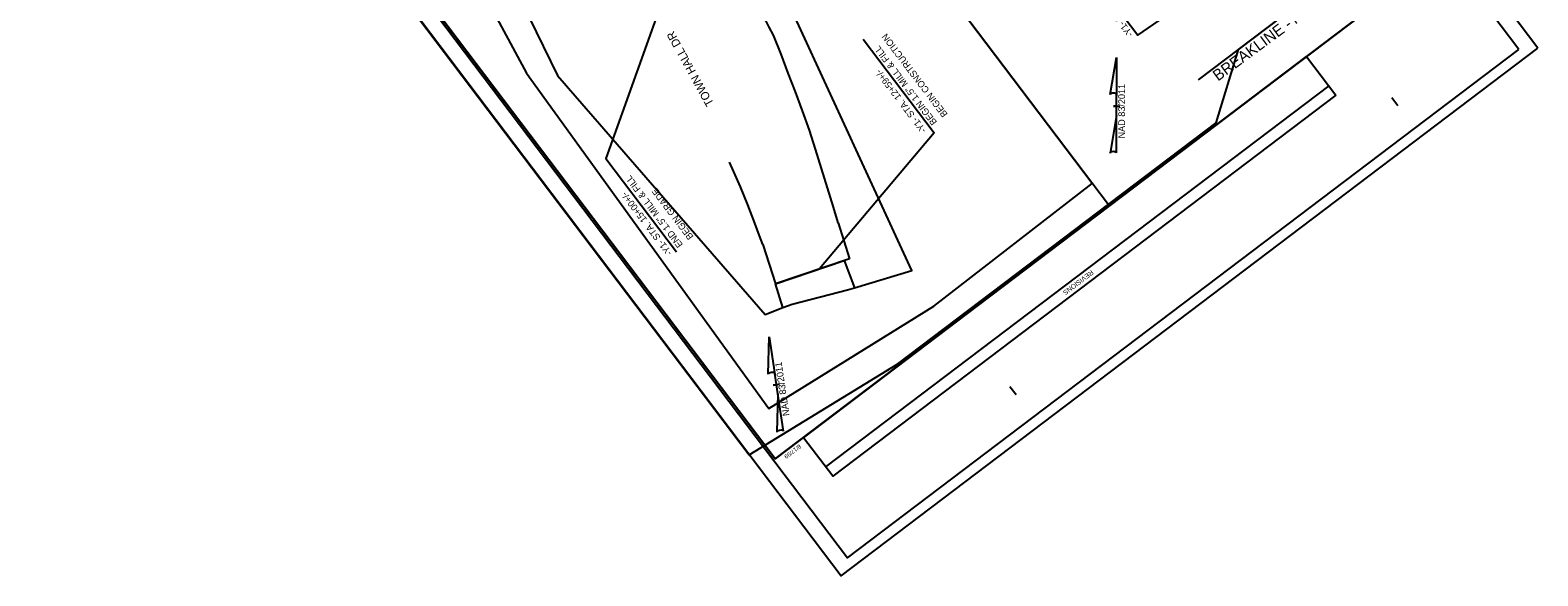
# Model space of a CAD drawing. Extents: x 2046295 to 2051060, y 758814 to 763808.
# Drawn here: x 2046295 to 2047429, y 758814 to 759224 of the extents above; entities that cross this region are included whole.
import ezdxf

# ---------------------------------------------------------------- set-up
doc = ezdxf.new("R2010")
doc.units = 0
for name, color, linetype in [('Matchline', 7, 'Continuous'), ('Matchline Text', 7, 'Continuous'), ('Prop Dimension', 7, 'Continuous'), ('Prop DSN Text', 7, 'Continuous'), ('Prop EOT', 7, 'Continuous'), ('Prop North Arrow NAD83 for Plan Sheets CELL', 7, 'Continuous'), ('Scratch_Level_0', 7, 'Continuous'), ('Scratch_Level_3', 7, 'Continuous'), ('Sheet Block Revision CELL', 7, 'Continuous'), ('Sheet Clip Boundary CELL', 7, 'Continuous'), ('Sheet Cutting Line CELL', 7, 'Continuous'), ('Sheet Plan CELL', 7, 'Continuous'), ('Sheet Plot Border Inside CELL', 7, 'Continuous'), ('Sheet Plot Border Outside CELL', 7, 'Continuous')]:
    doc.layers.add(name, color=color, linetype=linetype)

msp = doc.modelspace()

# ---------------------------------------------------------------- linework, layer by layer
at = {"layer": 'Matchline'}
msp.add_line((2047173.6, 759186.3), (2047315.8, 759294), dxfattribs=at)
at = {"layer": 'Prop DSN Text'}
for points in [[(2047066.4, 759301.2), (2047128, 759219.8), (2047216.9, 759281.2)], [(2046774.7, 759257.7), (2046728, 759127.3), (2046781.2, 759057.1)], [(2046921.6, 759216.8), (2046974.8, 759146.6), (2046888.8, 759044.2)]]:
    msp.add_lwpolyline(points, dxfattribs=at)
at = {"layer": 'Prop EOT'}
for p, q in [((2046902.8, 759078.9), (2046911.2, 759051.8)), ((2046846.1, 759062.5), (2046855.7, 759033.1)), ((2046911.2, 759051.8), (2046855.7, 759033.1))]:
    msp.add_line(p, q, dxfattribs=at)
for points in [[(2046902.8, 759078.9), (2046899.1, 759090.7), (2046894.6, 759105.1), (2046890.2, 759119.6), (2046885.7, 759134.2), (2046881.1, 759148.6), (2046876, 759162.9), (2046870.6, 759177.2), (2046865.2, 759191.4), (2046859.8, 759205.6), (2046854, 759219.9), (2046850.9, 759225.9), (2046848.5, 759230.5), (2046843.4, 759239.2), (2046839.3, 759246.2), (2046831.4, 759259.3), (2046823.3, 759272.2), (2046815.3, 759285.1), (2046813.3, 759288.9)], [(2046846.1, 759062.5), (2046843.7, 759069.2), (2046840.1, 759078.7), (2046834.8, 759092.3), (2046829.2, 759106), (2046824.4, 759117.3), (2046821.1, 759124.5)]]:
    msp.add_lwpolyline(points, dxfattribs=at)
at = {"layer": 'Prop North Arrow NAD83 for Plan Sheets CELL'}
for p, q in [((2047107.1, 759175.4), (2047112, 759203.2)), ((2047112.1, 759203.2), (2047112, 759203.2)), ((2047112.1, 759203.2), (2047112, 759203.2)), ((2047112.1, 759203.2), (2047112.1, 759174.5)), ((2047109.7, 759166.6), (2047109.6, 759166.6)), ((2047109.7, 759166.6), (2047114.5, 759166.6)), ((2047111.8, 759166.6), (2047109.7, 759166.6)), ((2047112.1, 759159.6), (2047112.1, 759175.3)), ((2047112.1, 759174.5), (2047112.1, 759175.3)), ((2047112.1, 759159.6), (2047107.1, 759131.3)), ((2047112.1, 759131.4), (2047112.1, 759159.6)), ((2046850.1, 758965.1), (2046850.9, 758993.3)), ((2046850.9, 758993.3), (2046850.9, 758993.3)), ((2046850.9, 758993.3), (2046850.9, 758993.3)), ((2046850.9, 758993.3), (2046855.2, 758965)), ((2046857.4, 758950.3), (2046855, 758965.8)), ((2046855.2, 758965), (2046855, 758965.8)), ((2046854, 758956.8), (2046853.9, 758956.8)), ((2046854, 758956.8), (2046858.7, 758957.5)), ((2046856.1, 758957.1), (2046854, 758956.8)), ((2046857.4, 758950.3), (2046856.6, 758921.5)), ((2046861.5, 758922.3), (2046857.4, 758950.3))]:
    msp.add_line(p, q, dxfattribs=at)
for centre, major_axis, start_param, end_param in [((2047109.6, 759175.1), (2.54, -0.02), 0.216388, 2.908219), ((2047109.6, 759131.2), (2.54, -0.02), 0.201328, 3.141593), ((2046852.6, 758965.2), (2.51, 0.36), 0.216388, 2.908219), ((2046859.1, 758921.8), (2.51, 0.36), 0.201328, 3.141593)]:
    msp.add_ellipse(centre, major_axis=major_axis, ratio=0.461098, start_param=start_param, end_param=end_param, dxfattribs=at)
at = {"layer": 'Scratch_Level_0'}
for points in [[(2046861, 759015.2), (2046855.7, 759033.1), (2046907.3, 759050.5), (2046914.9, 759030), (2046958.1, 759043), (2046838.9, 759301.8), (2046841, 759324.6), (2046814.7, 759365.3), (2046662.3, 759543.9), (2046574.8, 759483.5), (2046649.2, 759276.9), (2046691.7, 759189.6), (2046847.8, 759009.9)], [(2046861, 759015.2), (2046868.2, 759017.8), (2046909.8, 759028.4), (2046914.9, 759030), (2046958.1, 759043), (2046838.9, 759301.8), (2046841, 759324.6), (2046814.7, 759365.3), (2046662.3, 759543.9), (2046574.8, 759483.5), (2046649.2, 759276.9), (2046691.7, 759189.6), (2046847.8, 759009.9)]]:
    msp.add_lwpolyline(points, close=True, dxfattribs=at)
at = {"layer": 'Scratch_Level_3'}
msp.add_line((2046855.3, 759032.9), (2046907.3, 759050.5), dxfattribs=at)
msp.add_lwpolyline([(2046611.4, 759509.4), (2046530.1, 759447.9), (2046668.4, 759191.2), (2046850.7, 758939.3), (2046974.7, 759016.3), (2047093.8, 759108.4), (2046789, 759511), (2046715.5, 759608), (2046662.3, 759543.9)], close=True, dxfattribs=at)
at = {"layer": 'Sheet Block Revision CELL'}
for p, q in [((2047106.6, 759091.5), (2046563.3, 759809.1)), ((2047271.5, 759181.8), (2046893.3, 758895.4))]:
    msp.add_line(p, q, dxfattribs=at)
msp.add_lwpolyline([(2047276.8, 759174.8), (2046898.6, 758888.5), (2046876.6, 758917.4), (2047254.8, 759203.8)], close=True, dxfattribs=at)
at = {"layer": 'Sheet Clip Boundary CELL'}
msp.add_lwpolyline([(2046947.7, 758972.8), (2047186.9, 759153.9), (2047203.7, 759209.1), (2047315.8, 759294), (2046807.5, 759978.4), (2046429.8, 759650.9), (2046498.3, 759560.3), (2046397.2, 759483.7), (2046835.7, 758904.5)], close=True, dxfattribs=at)
at = {"layer": 'Sheet Cutting Line CELL'}
for p, q in [((2047428.8, 759210.2), (2046819, 760015.5)), ((2046295.2, 759618.9), (2046905, 758813.6)), ((2046905, 758813.6), (2047428.8, 759210.2))]:
    msp.add_line(p, q, dxfattribs=at)
at = {"layer": 'Sheet Plan CELL'}
for p, q in [((2047323.5, 759166.8), (2047319, 759172.8)), ((2047108.1, 759092.5), (2047108.1, 759092.5)), ((2047036.5, 758949.5), (2047031.9, 758955.5))]:
    msp.add_line(p, q, dxfattribs=at)
for points in [[(2046312.1, 759618.9), (2046855.4, 758901.4), (2047357.7, 759281.7), (2046814.4, 759999.2)], [(2047357.7, 759281.7), (2046855.4, 758901.4), (2046384.6, 759523.2), (2046456.4, 759577.6), (2046383.9, 759673.3), (2046814.4, 759999.2)]]:
    msp.add_lwpolyline(points, close=True, dxfattribs=at)
at = {"layer": 'Sheet Plot Border Inside CELL'}
msp.add_lwpolyline([(2047414.5, 759209.1), (2046811.1, 760006.1), (2046306.4, 759624), (2046909.8, 758827)], close=True, dxfattribs=at)
at = {"layer": 'Sheet Plot Border Outside CELL'}
msp.add_lwpolyline([(2047428.8, 759210.2), (2046819, 760015.5), (2046295.2, 759618.9), (2046905, 758813.6)], close=True, dxfattribs=at)

# ---------------------------------------------------------------- texts
at = {"layer": 'Matchline Text'}
msp.add_text('BREAKLINE -Y1- STA. 24+50', height=8.4, rotation=36.3424, dxfattribs=at).set_placement((2047188.3, 759185))
at = {"layer": 'Prop Dimension'}
msp.add_text('TOWN HALL DR', height=6.225, rotation=119.017, dxfattribs=at).set_placement((2046809.4, 759168.5))
at = {"layer": 'Prop DSN Text'}
for s, p in [('-Y1- STA. 25+00+/-', (2047124.8, 759220.8)), ('BEGIN 1.5" MILL & FILL', (2046977.3, 759154.6)), ('BEGIN CONSTRUCTION', (2046985.3, 759160.6)), ('-Y1- STA. 12+59+/-', (2046969.3, 759148.6)), ('END 1.5" MILL & FILL', (2046786.2, 759062.5)), ('-Y1- STA. 15+00+/-', (2046778.2, 759056.5)), ('BEGIN GRADE', (2046794.2, 759068.5))]:
    msp.add_text(s, height=5, rotation=127.1299, dxfattribs=at).set_placement(p)
at = {"layer": 'Prop North Arrow NAD83 for Plan Sheets CELL'}
for rotation, p in [(90, (2047118.4, 759142.3)), (98.4677, (2046866.2, 758934.1))]:
    msp.add_text('NAD 83/2011', height=5.1, rotation=rotation, dxfattribs=at).set_placement(p)
at = {"layer": 'Sheet Block Revision CELL'}
msp.add_text('REVISIONS', height=3.6, rotation=217.1294, dxfattribs=at).set_placement((2047093, 759043.6))
at = {"layer": 'Sheet Plan CELL'}
msp.add_text('8/17/99', height=3.15, rotation=217.1294, dxfattribs=at).set_placement((2046873.4, 758912.6))

doc.saveas('drawing.dxf')
